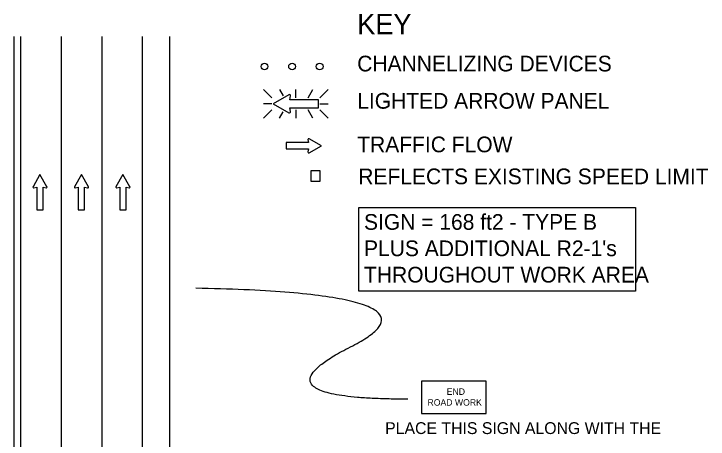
# Model space of a CAD drawing. Extents: x 16733 to 18475, y 7003 to 8205.
# Drawn here: x 16999.4 to 17410.2, y 7953.1 to 8204.8 of the extents above; entities that cross this region are included whole.
import ezdxf

# ---------------------------------------------------------------- set-up
doc = ezdxf.new("R2010")
doc.units = 0
for name, color, linetype in [('ALI_LEGAL_EX', 7, 'Continuous'), ('MT_SCRATCH_LEVEL_E', 7, 'Continuous'), ('PAVT_EDGE_EX', 7, 'Continuous'), ('TRAFFIC_SIGNS_PR', 7, 'Continuous'), ('TYPICAL_TEXT_DIMEN_EX', 7, 'Continuous'), ('TYPICAL_TEXT_DIMEN_PR', 7, 'Continuous')]:
    doc.layers.add(name, color=color, linetype=linetype)

msp = doc.modelspace()

# ---------------------------------------------------------------- linework, layer by layer
at = {"layer": 'ALI_LEGAL_EX'}
for p, q in [((17027.37, 8191.42), (17027.37, 7362.23)), ((17051.37, 8191.42), (17051.37, 7362.23)), ((17051.37, 8191.42), (17051.37, 7362.23))]:
    msp.add_line(p, q, dxfattribs=at)
for points in [[(17027.37, 8191.42), (17027.37, 8166.42)], [(17051.37, 8191.42), (17051.37, 8166.42)], [(17027.37, 8091.42), (17027.37, 8066.42)], [(17051.37, 8091.42), (17051.37, 8066.42)], [(17027.37, 7991.42), (17027.37, 7966.42)], [(17051.37, 7991.42), (17051.37, 7966.42)]]:
    msp.add_lwpolyline(points, dxfattribs=at)
at = {"layer": 'MT_SCRATCH_LEVEL_E'}
for p, q in [((17173.39, 8130.38), (17173.7, 8128.6)), ((17173.39, 8130.38), (17173.7, 8128.6)), ((17181.31, 8126.75), (17174.07, 8130.86)), ((17181.31, 8126.75), (17174.07, 8130.86)), ((17173.7, 8128.6), (17160.45, 8128.6)), ((17160.45, 8128.6), (17160.45, 8124.86)), ((17173.7, 8128.6), (17160.45, 8128.6)), ((17160.45, 8128.6), (17160.45, 8124.86)), ((17174.07, 8122.6), (17181.31, 8126.75)), ((17174.07, 8122.6), (17181.31, 8126.75)), ((17160.45, 8124.86), (17173.7, 8124.86)), ((17160.45, 8124.86), (17173.7, 8124.86)), ((17173.7, 8124.86), (17173.39, 8123.08)), ((17173.7, 8124.86), (17173.39, 8123.08)), ((17014.8, 8109.77), (17010.69, 8102.53)), ((17014.8, 8109.77), (17010.69, 8102.53)), ((17018.95, 8102.53), (17014.8, 8109.77)), ((17018.95, 8102.53), (17014.8, 8109.77)), ((17039.33, 8109.77), (17035.22, 8102.53)), ((17039.33, 8109.77), (17035.22, 8102.53)), ((17043.48, 8102.53), (17039.33, 8109.77)), ((17043.48, 8102.53), (17039.33, 8109.77)), ((17063.89, 8109.77), (17059.78, 8102.53)), ((17063.89, 8109.77), (17059.78, 8102.53)), ((17068.04, 8102.53), (17063.89, 8109.77)), ((17068.04, 8102.53), (17063.89, 8109.77)), ((17011.17, 8101.85), (17012.95, 8102.16)), ((17011.17, 8101.85), (17012.95, 8102.16)), ((17012.95, 8102.16), (17012.95, 8088.91)), ((17012.95, 8102.16), (17012.95, 8088.91)), ((17016.69, 8088.91), (17016.69, 8102.16)), ((17016.69, 8102.16), (17018.47, 8101.85)), ((17016.69, 8088.91), (17016.69, 8102.16)), ((17016.69, 8102.16), (17018.47, 8101.85)), ((17035.7, 8101.85), (17037.48, 8102.16)), ((17035.7, 8101.85), (17037.48, 8102.16)), ((17037.48, 8102.16), (17037.48, 8088.91)), ((17037.48, 8102.16), (17037.48, 8088.91)), ((17041.22, 8088.91), (17041.22, 8102.16)), ((17041.22, 8102.16), (17043, 8101.85)), ((17041.22, 8088.91), (17041.22, 8102.16)), ((17041.22, 8102.16), (17043, 8101.85)), ((17060.26, 8101.85), (17062.04, 8102.16)), ((17060.26, 8101.85), (17062.04, 8102.16)), ((17062.04, 8102.16), (17062.04, 8088.91)), ((17062.04, 8102.16), (17062.04, 8088.91)), ((17065.78, 8088.91), (17065.78, 8102.16)), ((17065.78, 8102.16), (17067.56, 8101.85)), ((17065.78, 8088.91), (17065.78, 8102.16)), ((17065.78, 8102.16), (17067.56, 8101.85)), ((17012.95, 8088.91), (17016.69, 8088.91)), ((17012.95, 8088.91), (17016.69, 8088.91)), ((17037.48, 8088.91), (17041.22, 8088.91)), ((17037.48, 8088.91), (17041.22, 8088.91)), ((17062.04, 8088.91), (17065.78, 8088.91)), ((17062.04, 8088.91), (17065.78, 8088.91))]:
    msp.add_line(p, q, dxfattribs=at)
for centre, start, end in [((17173.85, 8130.45), 60.4248, 189.9638), ((17173.85, 8130.45), 60.4248, 189.9638), ((17173.85, 8123.01), 170.0362, 299.7731), ((17173.85, 8123.01), 170.0362, 299.7731), ((17011.1, 8102.31), 150.4248, 279.9638), ((17011.1, 8102.31), 150.4248, 279.9638), ((17018.54, 8102.31), 260.0362, 29.7731), ((17018.54, 8102.31), 260.0362, 29.7731), ((17035.63, 8102.31), 150.4248, 279.9638), ((17035.63, 8102.31), 150.4248, 279.9638), ((17043.07, 8102.31), 260.0362, 29.7731), ((17043.07, 8102.31), 260.0362, 29.7731), ((17060.19, 8102.31), 150.4248, 279.9638), ((17060.19, 8102.31), 150.4248, 279.9638), ((17067.63, 8102.31), 260.0362, 29.7731), ((17067.63, 8102.31), 260.0362, 29.7731)]:
    msp.add_arc(centre, 0.463, start, end, dxfattribs=at)
at = {"layer": 'PAVT_EDGE_EX'}
for p, q in [((16999.37, 8191.42), (16999.37, 7362.23)), ((17003.37, 8191.42), (17003.37, 7362.23)), ((17075.37, 8191.42), (17075.37, 7362.23)), ((17091.37, 8191.42), (17091.37, 7362.23))]:
    msp.add_line(p, q, dxfattribs=at)
at = {"layer": 'TRAFFIC_SIGNS_PR'}
for p, q in [((17147.13, 8160.13), (17152.06, 8155.2)), ((17158.89, 8156.31), (17156.68, 8160.13)), ((17166.21, 8155.2), (17166.21, 8160.13)), ((17173.44, 8155.2), (17176.29, 8160.13)), ((17180.36, 8155.2), (17185.29, 8160.13)), ((17152.06, 8151.64), (17147.13, 8151.64)), ((17180.36, 8151.64), (17185.29, 8151.64)), ((17147.13, 8143.15), (17152.06, 8148.09)), ((17156.64, 8143.15), (17158.75, 8146.81)), ((17166.21, 8148.09), (17166.21, 8143.15)), ((17176.34, 8143.15), (17173.49, 8148.09)), ((17180.36, 8148.09), (17185.29, 8143.15))]:
    msp.add_line(p, q, dxfattribs=at)
for points in [[(17162.14, 8156.92), (17152.84, 8151.64), (17162.14, 8146.32)], [(17163.01, 8146.95), (17162.61, 8149.22), (17179.62, 8149.22), (17179.62, 8154.02), (17162.61, 8154.02), (17163.01, 8156.3)]]:
    msp.add_lwpolyline(points, dxfattribs=at)
for points in [[(17175.08, 8105.81), (17180.67, 8105.81), (17180.67, 8111.98), (17175.08, 8111.98)], [(17240.52, 7968.21), (17278.92, 7968.21), (17278.92, 7987.41), (17240.52, 7987.41)]]:
    msp.add_lwpolyline(points, close=True, dxfattribs=at)
for centre in [(17147.69, 8173.67), (17163.99, 8173.67), (17180.29, 8173.67)]:
    msp.add_circle(centre, 2, dxfattribs=at)
for centre, radius, start, end in [((17162.42, 8156.4), 0.598, 350.7308, 118.8916), ((17162.42, 8146.85), 0.597, 241.4833, 9.9593)]:
    msp.add_arc(centre, radius, start, end, dxfattribs=at)
at = {"layer": 'TYPICAL_TEXT_DIMEN_EX'}
msp.add_lwpolyline([(17203.58, 8090.18), (17367.11, 8090.18), (17367.11, 8040.67), (17203.58, 8040.67)], close=True, dxfattribs=at)
at = {"layer": 'TYPICAL_TEXT_DIMEN_PR'}
msp.add_open_spline([(17232.5, 7976.78), (17137.04, 7976.78), (17261.2, 8039.33), (17107.09, 8042.46)], degree=2, dxfattribs=at)

# ---------------------------------------------------------------- texts
at = {"layer": 'TRAFFIC_SIGNS_PR'}
for s, height, p in [('END', 3.831, (17255.52, 7979.34)), ('ROAD WORK', 3.831, (17244.13, 7972.95)), ('PLACE THIS SIGN ALONG WITH THE', 7, (17219.06, 7956.15))]:
    msp.add_text(s, height=height, dxfattribs=at).set_placement(p)
at = {"layer": 'TYPICAL_TEXT_DIMEN_EX'}
for s, height, p in [('KEY', 12, (17202.53, 8192.78)), ('CHANNELIZING DEVICES', 9.3, (17202.53, 8170.73)), ('LIGHTED ARROW PANEL', 9.3, (17202.53, 8148.68)), ('TRAFFIC FLOW', 9.3, (17202.53, 8122.88)), ('REFLECTS EXISTING SPEED LIMIT', 9.3, (17203.15, 8103.97)), ('SIGN = 168 ft2 - TYPE B', 9.3, (17206.55, 8077.01)), ("PLUS ADDITIONAL R2-1's", 9.3, (17206.55, 8061.41)), ('THROUGHOUT WORK AREA', 9.3, (17206.55, 8045.81))]:
    msp.add_text(s, height=height, dxfattribs=at).set_placement(p)

doc.saveas('drawing.dxf')
